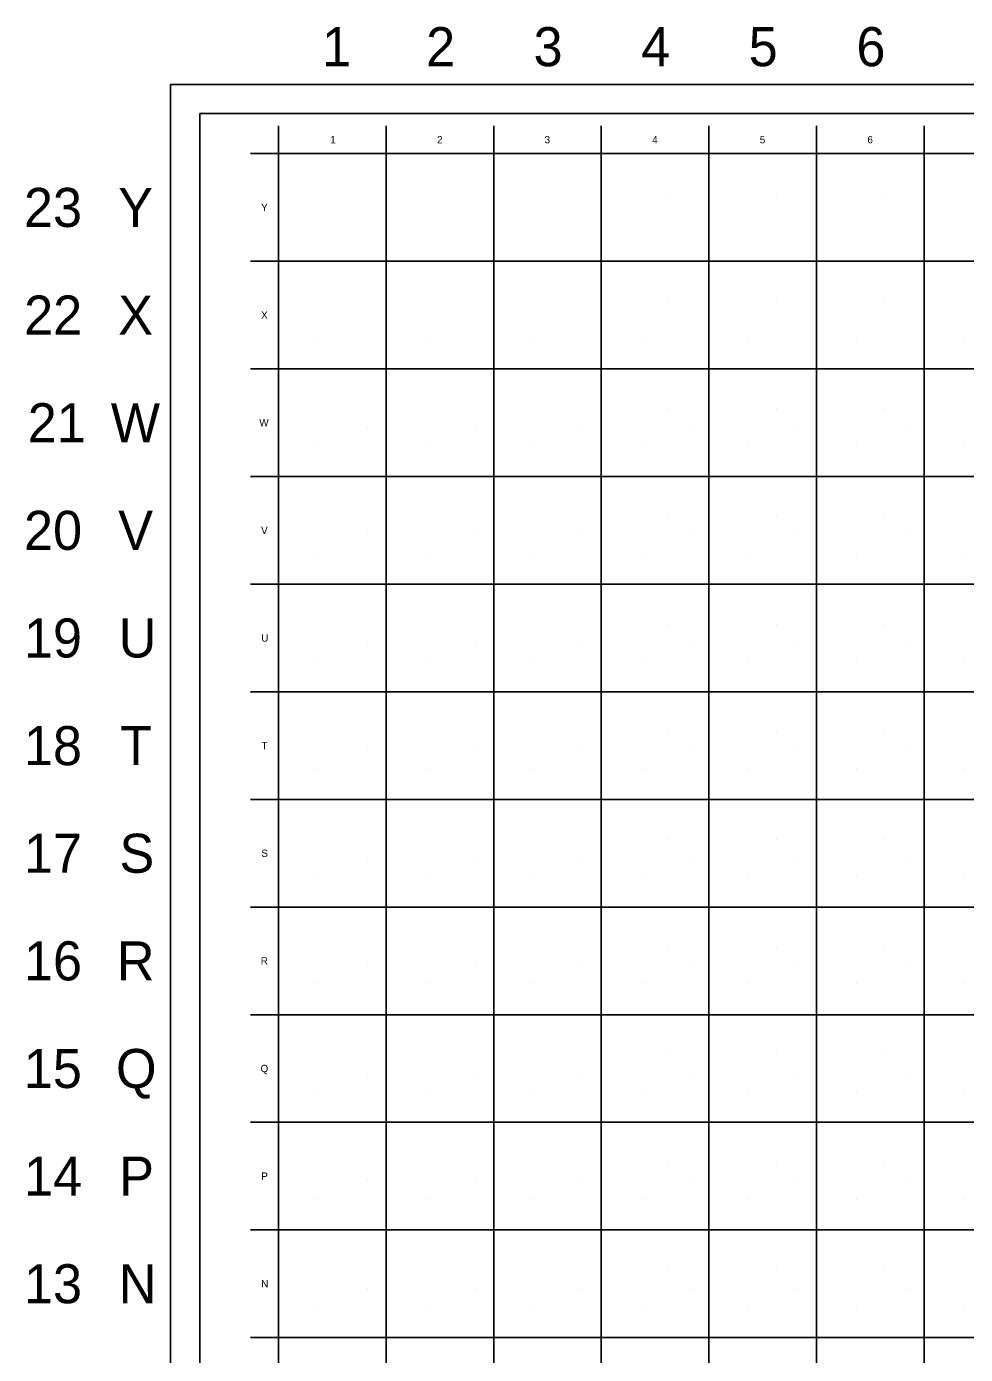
# Model space of a CAD drawing. Extents: x -0.05 to 1.19, y 0 to 0.86.
# Drawn here: x -0.0468 to 0.2585, y 0.428 to 0.8598 of the extents above; entities that cross this region are included whole.
import ezdxf

# ---------------------------------------------------------------- set-up
doc = ezdxf.new("R2010")
doc.units = 0
for name, color, linetype in [('G-ANNO-NPLT', 7, 'Continuous'), ('G-ANNO-TEXT', 7, 'Continuous'), ('G-ANNO-TTLB', 7, 'Continuous'), ('G-ANNO-TTLB-GRID', 7, 'Continuous')]:
    doc.layers.add(name, color=color, linetype=linetype)

msp = doc.modelspace()

# ---------------------------------------------------------------- linework, layer by layer
at = {"layer": 'G-ANNO-NPLT'}
for p, q in [((0.16207, 0.80547), (0.16207, 0.80547)), ((0.19708, 0.80547), (0.19708, 0.80547)), ((0.23207, 0.80547), (0.23207, 0.80547)), ((0.16207, 0.77047), (0.16207, 0.77047)), ((0.19708, 0.77047), (0.19708, 0.77047)), ((0.23207, 0.77047), (0.23207, 0.77047)), ((0.04807, 0.75847), (0.04807, 0.75847)), ((0.08307, 0.75847), (0.08307, 0.75847)), ((0.11807, 0.75847), (0.11807, 0.75847)), ((0.15307, 0.75847), (0.15307, 0.75847)), ((0.18807, 0.75847), (0.18807, 0.75847)), ((0.22307, 0.75847), (0.22307, 0.75847)), ((0.25807, 0.75847), (0.25807, 0.75847)), ((0.16207, 0.73547), (0.16207, 0.73547)), ((0.19708, 0.73547), (0.19708, 0.73547)), ((0.23207, 0.73547), (0.23207, 0.73547)), ((0.06407, 0.72947), (0.06407, 0.72947)), ((0.09907, 0.72947), (0.09907, 0.72947)), ((0.13407, 0.72947), (0.13407, 0.72947)), ((0.16908, 0.72947), (0.16908, 0.72947)), ((0.20407, 0.72947), (0.20407, 0.72947)), ((0.23907, 0.72947), (0.23907, 0.72947)), ((0.04807, 0.72347), (0.04807, 0.72347)), ((0.08307, 0.72347), (0.08307, 0.72347)), ((0.11807, 0.72347), (0.11807, 0.72347)), ((0.15307, 0.72347), (0.15307, 0.72347)), ((0.18807, 0.72347), (0.18807, 0.72347)), ((0.22307, 0.72347), (0.22307, 0.72347)), ((0.25807, 0.72347), (0.25807, 0.72347)), ((0.16207, 0.70047), (0.16207, 0.70047)), ((0.19708, 0.70047), (0.19708, 0.70047)), ((0.23207, 0.70047), (0.23207, 0.70047)), ((0.06407, 0.69447), (0.06407, 0.69447)), ((0.09907, 0.69447), (0.09907, 0.69447)), ((0.13407, 0.69447), (0.13407, 0.69447)), ((0.16908, 0.69447), (0.16908, 0.69447)), ((0.20407, 0.69447), (0.20407, 0.69447)), ((0.23907, 0.69447), (0.23907, 0.69447)), ((0.04807, 0.68847), (0.04807, 0.68847)), ((0.08307, 0.68847), (0.08307, 0.68847)), ((0.11807, 0.68847), (0.11807, 0.68847)), ((0.15307, 0.68847), (0.15307, 0.68847)), ((0.18807, 0.68847), (0.18807, 0.68847)), ((0.22307, 0.68847), (0.22307, 0.68847)), ((0.25807, 0.68847), (0.25807, 0.68847)), ((0.16207, 0.66547), (0.16207, 0.66547)), ((0.19708, 0.66547), (0.19708, 0.66547)), ((0.23207, 0.66547), (0.23207, 0.66547)), ((0.06407, 0.65947), (0.06407, 0.65947)), ((0.09907, 0.65947), (0.09907, 0.65947)), ((0.13407, 0.65947), (0.13407, 0.65947)), ((0.16908, 0.65947), (0.16908, 0.65947)), ((0.20407, 0.65947), (0.20407, 0.65947)), ((0.23907, 0.65947), (0.23907, 0.65947)), ((0.04807, 0.65347), (0.04807, 0.65347)), ((0.08307, 0.65347), (0.08307, 0.65347)), ((0.11807, 0.65347), (0.11807, 0.65347)), ((0.15307, 0.65347), (0.15307, 0.65347)), ((0.18807, 0.65347), (0.18807, 0.65347)), ((0.22307, 0.65347), (0.22307, 0.65347)), ((0.25807, 0.65347), (0.25807, 0.65347)), ((0.16207, 0.63047), (0.16207, 0.63047)), ((0.19708, 0.63047), (0.19708, 0.63047)), ((0.23207, 0.63047), (0.23207, 0.63047)), ((0.06407, 0.62447), (0.06407, 0.62447)), ((0.09907, 0.62447), (0.09907, 0.62447)), ((0.13407, 0.62447), (0.13407, 0.62447)), ((0.16908, 0.62447), (0.16908, 0.62447)), ((0.20407, 0.62447), (0.20407, 0.62447)), ((0.23907, 0.62447), (0.23907, 0.62447)), ((0.04807, 0.61847), (0.04807, 0.61847)), ((0.08307, 0.61847), (0.08307, 0.61847)), ((0.11807, 0.61847), (0.11807, 0.61847)), ((0.15307, 0.61847), (0.15307, 0.61847)), ((0.18807, 0.61847), (0.18807, 0.61847)), ((0.22307, 0.61847), (0.22307, 0.61847)), ((0.25807, 0.61847), (0.25807, 0.61847)), ((0.16207, 0.59547), (0.16207, 0.59547)), ((0.19708, 0.59547), (0.19708, 0.59547)), ((0.23207, 0.59547), (0.23207, 0.59547)), ((0.06407, 0.58947), (0.06407, 0.58947)), ((0.09907, 0.58947), (0.09907, 0.58947)), ((0.13407, 0.58947), (0.13407, 0.58947)), ((0.16908, 0.58947), (0.16908, 0.58947)), ((0.20407, 0.58947), (0.20407, 0.58947)), ((0.23907, 0.58947), (0.23907, 0.58947)), ((0.04807, 0.58347), (0.04807, 0.58347)), ((0.08307, 0.58347), (0.08307, 0.58347)), ((0.11807, 0.58347), (0.11807, 0.58347)), ((0.15307, 0.58347), (0.15307, 0.58347)), ((0.18807, 0.58347), (0.18807, 0.58347)), ((0.22307, 0.58347), (0.22307, 0.58347)), ((0.25807, 0.58347), (0.25807, 0.58347)), ((0.16207, 0.56047), (0.16207, 0.56047)), ((0.19708, 0.56047), (0.19708, 0.56047)), ((0.23207, 0.56047), (0.23207, 0.56047)), ((0.06407, 0.55447), (0.06407, 0.55447)), ((0.09907, 0.55447), (0.09907, 0.55447)), ((0.13407, 0.55447), (0.13407, 0.55447)), ((0.16908, 0.55447), (0.16908, 0.55447)), ((0.20407, 0.55447), (0.20407, 0.55447)), ((0.23907, 0.55447), (0.23907, 0.55447)), ((0.04807, 0.54847), (0.04807, 0.54847)), ((0.08307, 0.54847), (0.08307, 0.54847)), ((0.11807, 0.54847), (0.11807, 0.54847)), ((0.15307, 0.54847), (0.15307, 0.54847)), ((0.18807, 0.54847), (0.18807, 0.54847)), ((0.22307, 0.54847), (0.22307, 0.54847)), ((0.25807, 0.54847), (0.25807, 0.54847)), ((0.16207, 0.52547), (0.16207, 0.52547)), ((0.19708, 0.52547), (0.19708, 0.52547)), ((0.23207, 0.52547), (0.23207, 0.52547)), ((0.06407, 0.51947), (0.06407, 0.51947)), ((0.09907, 0.51947), (0.09907, 0.51947)), ((0.13407, 0.51947), (0.13407, 0.51947)), ((0.16908, 0.51947), (0.16908, 0.51947)), ((0.20407, 0.51947), (0.20407, 0.51947)), ((0.23907, 0.51947), (0.23907, 0.51947)), ((0.04807, 0.51347), (0.04807, 0.51347)), ((0.08307, 0.51347), (0.08307, 0.51347)), ((0.11807, 0.51347), (0.11807, 0.51347)), ((0.15307, 0.51347), (0.15307, 0.51347)), ((0.18807, 0.51347), (0.18807, 0.51347)), ((0.22307, 0.51347), (0.22307, 0.51347)), ((0.25807, 0.51347), (0.25807, 0.51347)), ((0.16207, 0.49047), (0.16207, 0.49047)), ((0.19708, 0.49047), (0.19708, 0.49047)), ((0.23207, 0.49047), (0.23207, 0.49047)), ((0.06407, 0.48447), (0.06407, 0.48447)), ((0.09907, 0.48447), (0.09907, 0.48447)), ((0.13407, 0.48447), (0.13407, 0.48447)), ((0.16908, 0.48447), (0.16908, 0.48447)), ((0.20407, 0.48447), (0.20407, 0.48447)), ((0.23907, 0.48447), (0.23907, 0.48447)), ((0.04807, 0.47847), (0.04807, 0.47847)), ((0.08307, 0.47847), (0.08307, 0.47847)), ((0.11807, 0.47847), (0.11807, 0.47847)), ((0.15307, 0.47847), (0.15307, 0.47847)), ((0.18807, 0.47847), (0.18807, 0.47847)), ((0.22307, 0.47847), (0.22307, 0.47847)), ((0.25807, 0.47847), (0.25807, 0.47847)), ((0.16207, 0.45547), (0.16207, 0.45547)), ((0.19708, 0.45547), (0.19708, 0.45547)), ((0.23207, 0.45547), (0.23207, 0.45547)), ((0.06407, 0.44947), (0.06407, 0.44947)), ((0.09907, 0.44947), (0.09907, 0.44947)), ((0.13407, 0.44947), (0.13407, 0.44947)), ((0.16908, 0.44947), (0.16908, 0.44947)), ((0.20407, 0.44947), (0.20407, 0.44947)), ((0.23907, 0.44947), (0.23907, 0.44947)), ((0.04807, 0.44347), (0.04807, 0.44347)), ((0.08307, 0.44347), (0.08307, 0.44347)), ((0.11807, 0.44347), (0.11807, 0.44347)), ((0.15307, 0.44347), (0.15307, 0.44347)), ((0.18807, 0.44347), (0.18807, 0.44347)), ((0.22307, 0.44347), (0.22307, 0.44347)), ((0.25807, 0.44347), (0.25807, 0.44347))]:
    msp.add_line(p, q, dxfattribs=at)
msp.add_lwpolyline([(0.00952, 0.83147), (1.17948, 0.83147), (1.17948, 0.00952), (0.00952, 0.00952)], close=True, dxfattribs=at)
at = {"layer": 'G-ANNO-TEXT'}
for p, q in [((0.03507, 0.81847), (0.03507, 0.82753)), ((0.07007, 0.81847), (0.07007, 0.82753)), ((0.10508, 0.81847), (0.10508, 0.82753)), ((0.14008, 0.81847), (0.14008, 0.82753)), ((0.17507, 0.81847), (0.17507, 0.82753)), ((0.21007, 0.81847), (0.21007, 0.82753)), ((0.24507, 0.81847), (0.24507, 0.82753)), ((0.03507, 0.81847), (0.02601, 0.81847)), ((0.03507, 0.78347), (0.02601, 0.78347)), ((0.03507, 0.74847), (0.02601, 0.74847)), ((0.03507, 0.71347), (0.02601, 0.71347)), ((0.03507, 0.67847), (0.02601, 0.67847)), ((0.03507, 0.64347), (0.02601, 0.64347)), ((0.03507, 0.60847), (0.02601, 0.60847)), ((0.03507, 0.57347), (0.02601, 0.57347)), ((0.03507, 0.53847), (0.02601, 0.53847)), ((0.03507, 0.50347), (0.02601, 0.50347)), ((0.03507, 0.46847), (0.02601, 0.46847)), ((0.03507, 0.43347), (0.02601, 0.43347))]:
    msp.add_line(p, q, dxfattribs=at)
at = {"layer": 'G-ANNO-TTLB'}
for points in [[(0, 0.841), (1.189, 0.841), (1.189, 0), (0, 0)], [(0.03507, 0.81847), (1.17009, 0.81847), (1.17009, 0.01347), (0.03507, 0.01347)]]:
    msp.add_lwpolyline(points, close=True, dxfattribs=at)
at = {"layer": 'G-ANNO-TTLB-GRID'}
for p, q in [((0.07007, 0.81847), (0.07007, 0.01347)), ((0.10508, 0.81847), (0.10508, 0.01347)), ((0.14008, 0.81847), (0.14008, 0.01347)), ((0.17507, 0.81847), (0.17507, 0.01347)), ((0.21007, 0.81847), (0.21007, 0.01347)), ((0.24507, 0.81847), (0.24507, 0.01347)), ((0.03507, 0.78347), (1.17009, 0.78347)), ((0.03507, 0.74847), (1.17009, 0.74847)), ((0.03507, 0.71347), (1.17009, 0.71347)), ((0.03507, 0.67847), (1.17009, 0.67847)), ((0.03507, 0.64347), (1.17009, 0.64347)), ((0.03507, 0.60847), (1.17009, 0.60847)), ((0.03507, 0.57347), (1.12007, 0.57347)), ((0.03507, 0.53847), (1.12007, 0.53847)), ((0.03507, 0.50347), (1.12007, 0.50347)), ((0.03507, 0.46847), (1.12007, 0.46847)), ((0.03507, 0.43347), (1.12007, 0.43347))]:
    msp.add_line(p, q, dxfattribs=at)

# ---------------------------------------------------------------- texts
at = {"layer": 'G-ANNO-NPLT'}
for s, p in [('1', (0.04927, 0.8469)), ('2', (0.08311, 0.8469)), ('3', (0.11804, 0.8469)), ('4', (0.15307, 0.8469)), ('5', (0.188, 0.8469)), ('6', (0.22304, 0.8469)), ('23', (-0.04768, 0.79462)), ('Y', (-0.01703, 0.79462)), ('22', (-0.04762, 0.75962)), ('X', (-0.01704, 0.75962)), ('21', (-0.04646, 0.72462)), ('W', (-0.01945, 0.72462)), ('20', (-0.04766, 0.68962)), ('V', (-0.01702, 0.68962)), ('19', (-0.04769, 0.65462)), ('U', (-0.01687, 0.65462)), ('18', (-0.04769, 0.61962)), ('T', (-0.01642, 0.61962)), ('17', (-0.04768, 0.58462)), ('S', (-0.01663, 0.58462)), ('16', (-0.04768, 0.54962)), ('R', (-0.01746, 0.54962)), ('15', (-0.04773, 0.51462)), ('Q', (-0.01775, 0.51462)), ('14', (-0.04766, 0.47962)), ('P', (-0.01671, 0.47962)), ('13', (-0.04768, 0.44462)), ('N', (-0.01686, 0.44462))]:
    msp.add_text(s, height=0.0127, dxfattribs=at).set_placement(p)
at = {"layer": 'G-ANNO-TEXT'}
for s, p in [('1', (0.05192, 0.8218)), ('2', (0.08665, 0.8218)), ('3', (0.12163, 0.8218)), ('4', (0.15664, 0.8218)), ('5', (0.19162, 0.8218)), ('6', (0.22663, 0.8218)), ('Y', (0.02944, 0.79977)), ('X', (0.02944, 0.76477)), ('W', (0.02887, 0.72977)), ('V', (0.02944, 0.69477)), ('U', (0.02948, 0.65977)), ('T', (0.02958, 0.62477)), ('S', (0.02953, 0.58977)), ('R', (0.02933, 0.55477)), ('Q', (0.02927, 0.51977)), ('P', (0.02951, 0.48477)), ('N', (0.02948, 0.44977))]:
    msp.add_text(s, height=0.0024, dxfattribs=at).set_placement(p)

doc.saveas('drawing.dxf')
